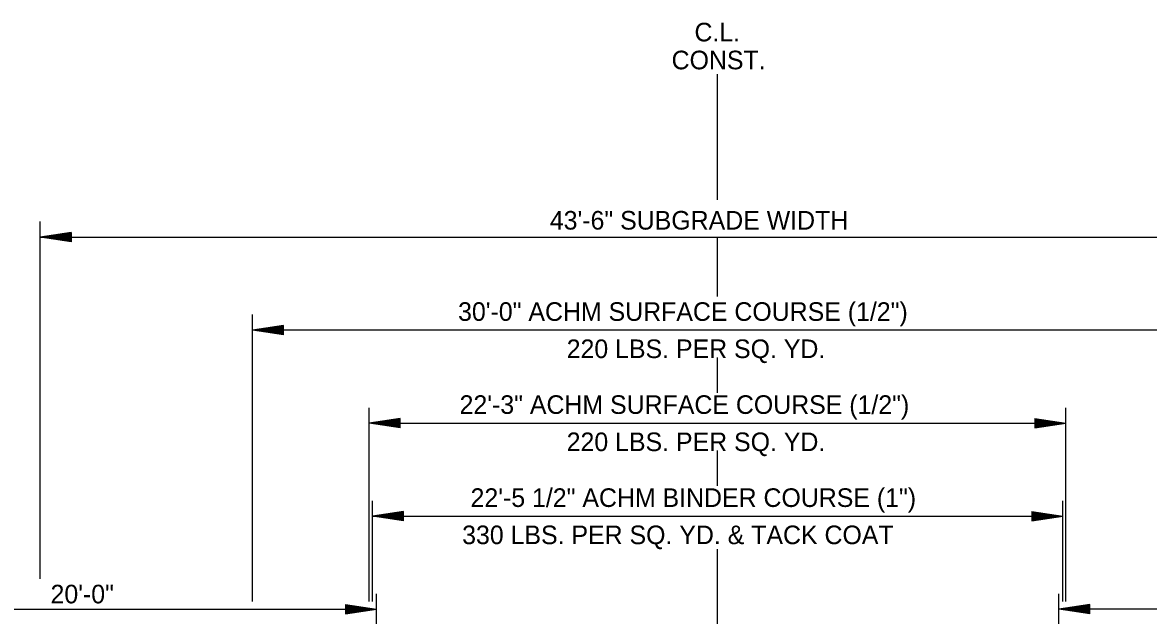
# Model space of a CAD drawing. Extents: x -900 to 15312, y 1857 to 2945.
# Drawn here: x 3840 to 4203.1, y 2524 to 2715.2 of the extents above; entities that cross this region are included whole.
import ezdxf

# ---------------------------------------------------------------- set-up
doc = ezdxf.new("R2010")
doc.units = 0
for name, color, linetype in [('R_Annotation', 7, 'Continuous'), ('R_Centerline', 7, 'Continuous'), ('R_Dimension', 7, 'Continuous')]:
    doc.layers.add(name, color=color, linetype=linetype)

msp = doc.modelspace()

# ---------------------------------------------------------------- linework, layer by layer
at = {"layer": 'R_Centerline'}
for p, q in [((4064.16, 2657.99), (4064.16, 2698.53)), ((4064.16, 2626.91), (4064.16, 2646.02)), ((4064.16, 2595.8), (4064.16, 2607.22)), ((4064.16, 2565.8), (4064.16, 2577.22)), ((4064.16, 2466.69), (4064.16, 2545.4))]:
    msp.add_line(p, q, dxfattribs=at)
at = {"layer": 'R_Dimension'}
for p, q in [((3845.74, 2535.88), (3845.74, 2651.02)), ((3855.74, 2647.52), (3845.74, 2646.02)), ((3855.74, 2647.27), (3847.41, 2646.02)), ((3855.74, 2647.02), (3849.13, 2646.02)), ((3855.74, 2646.77), (3850.79, 2646.02)), ((3855.74, 2647.52), (3855.74, 2644.52)), ((3845.74, 2646.02), (4282.59, 2646.02)), ((3855.74, 2644.52), (3845.74, 2646.02)), ((3855.74, 2644.77), (3847.41, 2646.02)), ((3855.74, 2645.03), (3849.13, 2646.02)), ((3855.74, 2645.28), (3850.79, 2646.02)), ((3855.74, 2646.51), (3852.49, 2646.02)), ((3855.74, 2645.53), (3852.49, 2646.02)), ((3855.74, 2646.26), (3854.16, 2646.02)), ((3855.74, 2645.79), (3854.16, 2646.02)), ((3914.16, 2528.52), (3914.16, 2621.02)), ((3924.16, 2617.52), (3914.16, 2616.02)), ((4214.16, 2616.02), (3914.16, 2616.02)), ((3924.16, 2614.52), (3914.16, 2616.02)), ((3924.16, 2617.27), (3915.83, 2616.02)), ((3924.16, 2614.77), (3915.83, 2616.02)), ((3924.16, 2617.02), (3917.55, 2616.02)), ((3924.16, 2615.03), (3917.55, 2616.02)), ((3924.16, 2616.77), (3919.22, 2616.02)), ((3924.16, 2615.28), (3919.22, 2616.02)), ((3924.16, 2616.51), (3920.91, 2616.02)), ((3924.16, 2615.54), (3920.91, 2616.02)), ((3924.16, 2616.26), (3922.58, 2616.02)), ((3924.16, 2615.79), (3922.58, 2616.02)), ((3924.16, 2614.52), (3924.16, 2617.52)), ((3951.85, 2528.52), (3951.85, 2591.02)), ((4176.48, 2528.52), (4176.48, 2591.02)), ((3961.85, 2587.52), (3951.85, 2586.02)), ((3961.85, 2584.52), (3951.85, 2586.02)), ((3952.9, 2586.02), (4175.43, 2586.02)), ((3961.85, 2587.27), (3953.52, 2586.02)), ((3961.85, 2584.77), (3953.52, 2586.02)), ((3961.85, 2587.02), (3955.24, 2586.02)), ((3961.85, 2585.03), (3955.24, 2586.02)), ((3961.85, 2586.77), (3956.9, 2586.02)), ((3961.85, 2585.28), (3956.9, 2586.02)), ((3961.85, 2586.51), (3958.6, 2586.02)), ((3961.85, 2585.54), (3958.6, 2586.02)), ((3961.85, 2586.26), (3960.27, 2586.02)), ((3961.85, 2585.79), (3960.27, 2586.02)), ((3961.85, 2584.52), (3961.85, 2587.52)), ((4166.48, 2587.52), (4176.48, 2586.02)), ((4166.48, 2587.52), (4166.48, 2584.52)), ((4166.48, 2587.27), (4174.81, 2586.02)), ((4166.48, 2587.02), (4173.09, 2586.02)), ((4166.48, 2586.77), (4171.42, 2586.02)), ((4166.48, 2586.51), (4169.73, 2586.02)), ((4166.48, 2586.26), (4168.06, 2586.02)), ((4166.48, 2584.52), (4176.48, 2586.02)), ((4166.48, 2585.53), (4169.73, 2586.02)), ((4166.48, 2585.03), (4173.09, 2586.02)), ((4166.48, 2584.77), (4174.81, 2586.02)), ((4166.48, 2585.28), (4171.42, 2586.02)), ((4166.48, 2585.79), (4168.06, 2586.02)), ((3952.9, 2528.52), (3952.9, 2561.02)), ((4175.43, 2528.52), (4175.43, 2561.02)), ((3962.9, 2557.52), (3952.9, 2556.02)), ((3952.9, 2556.02), (4175.43, 2556.02)), ((3962.9, 2554.52), (3952.9, 2556.02)), ((3962.9, 2557.27), (3954.57, 2556.02)), ((3962.9, 2554.77), (3954.57, 2556.02)), ((3962.9, 2557.02), (3956.29, 2556.02)), ((3962.9, 2555.03), (3956.29, 2556.02)), ((3962.9, 2556.77), (3957.96, 2556.02)), ((3962.9, 2555.28), (3957.96, 2556.02)), ((3962.9, 2556.51), (3959.65, 2556.02)), ((3962.9, 2555.54), (3959.65, 2556.02)), ((3962.9, 2556.26), (3961.32, 2556.02)), ((3962.9, 2555.79), (3961.32, 2556.02)), ((3962.9, 2554.52), (3962.9, 2557.52)), ((4165.43, 2557.52), (4175.43, 2556.02)), ((4165.43, 2557.52), (4165.43, 2554.52)), ((4165.43, 2557.27), (4173.76, 2556.02)), ((4165.43, 2557.02), (4172.04, 2556.02)), ((4165.43, 2556.77), (4170.38, 2556.02)), ((4165.43, 2556.51), (4168.68, 2556.02)), ((4165.43, 2556.26), (4167.01, 2556.02)), ((4165.43, 2554.52), (4175.43, 2556.02)), ((4165.43, 2555.53), (4168.68, 2556.02)), ((4165.43, 2555.03), (4172.04, 2556.02)), ((4165.43, 2554.77), (4173.76, 2556.02)), ((4165.43, 2555.28), (4170.38, 2556.02)), ((4165.43, 2555.79), (4167.01, 2556.02)), ((3954.16, 2506.02), (3954.16, 2531.02)), ((4174.16, 2506.02), (4174.16, 2531.02)), ((3944.16, 2527.52), (3954.16, 2526.02)), ((3944.16, 2527.52), (3944.16, 2524.52)), ((3944.16, 2527.27), (3952.49, 2526.02)), ((3944.16, 2527.02), (3950.77, 2526.02)), ((4184.16, 2527.52), (4174.16, 2526.02)), ((4184.16, 2527.27), (4175.83, 2526.02)), ((4184.16, 2527.02), (4177.55, 2526.02)), ((4184.16, 2524.52), (4184.16, 2527.52)), ((3754.16, 2526.02), (3954.16, 2526.02)), ((3944.16, 2526.77), (3949.11, 2526.02)), ((3944.16, 2526.51), (3947.41, 2526.02)), ((3944.16, 2526.26), (3945.74, 2526.02)), ((3944.16, 2524.52), (3954.16, 2526.02)), ((3944.16, 2525.53), (3947.41, 2526.02)), ((3944.16, 2525.03), (3950.77, 2526.02)), ((3944.16, 2524.77), (3952.49, 2526.02)), ((3944.16, 2525.28), (3949.11, 2526.02)), ((3944.16, 2525.79), (3945.74, 2526.02)), ((4374.16, 2526.02), (4174.16, 2526.02)), ((4184.16, 2524.52), (4174.16, 2526.02)), ((4184.16, 2524.77), (4175.83, 2526.02)), ((4184.16, 2525.03), (4177.55, 2526.02)), ((4184.16, 2526.77), (4179.22, 2526.02)), ((4184.16, 2525.28), (4179.22, 2526.02)), ((4184.16, 2526.51), (4180.91, 2526.02)), ((4184.16, 2525.54), (4180.91, 2526.02)), ((4184.16, 2526.26), (4182.58, 2526.02)), ((4184.16, 2525.79), (4182.58, 2526.02))]:
    msp.add_line(p, q, dxfattribs=at)

# ---------------------------------------------------------------- texts
at = {"layer": 'R_Annotation'}
for s, p in [('C.L.', (4056.7, 2709.13)), ('CONST.', (4049.33, 2700.13)), ('43\'-6" SUBGRADE WIDTH', (4010.07, 2648.45)), ('30\'-0" ACHM SURFACE COURSE (1/2")', (3980.49, 2619.02)), ('220 LBS. PER SQ. YD.', (4015.5, 2607.02)), ('22\'-3" ACHM SURFACE COURSE (1/2")', (3980.97, 2589.02)), ('220 LBS. PER SQ. YD.', (4015.5, 2577.02)), ('22\'-5 1/2" ACHM BINDER COURSE (1")', (3984.51, 2559.02)), ('330 LBS. PER SQ. YD. & TACK COAT', (3981.8, 2547.02)), ('20\'-0"', (3849.08, 2527.93))]:
    msp.add_text(s, height=6, dxfattribs=at).set_placement(p)

doc.saveas('drawing.dxf')
